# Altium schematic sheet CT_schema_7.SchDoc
size 250 x 169 mm
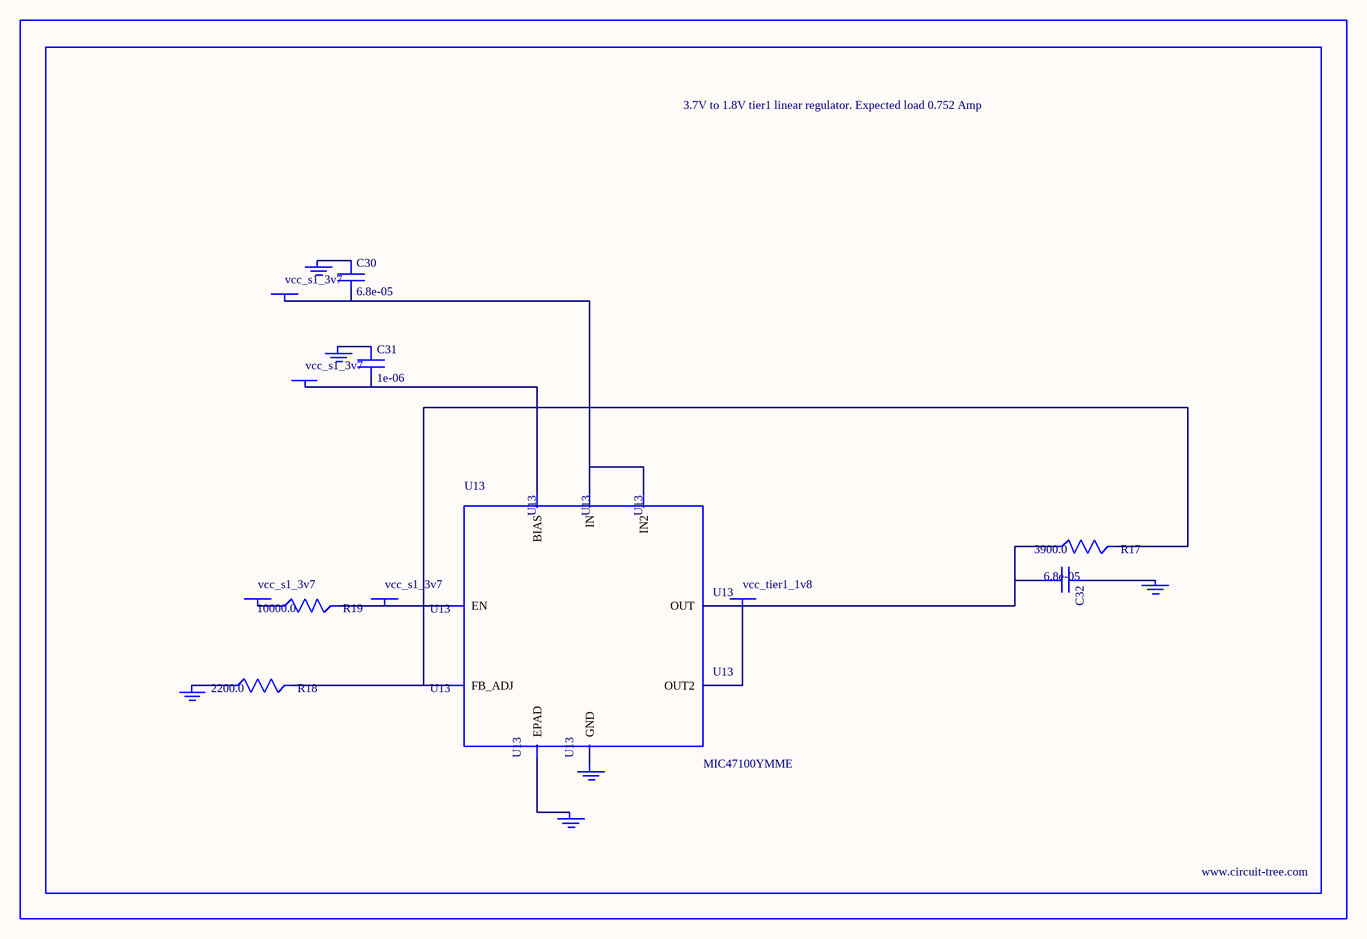
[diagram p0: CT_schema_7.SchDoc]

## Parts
BORDER6  (no value)
C30  6.8e-05  [2220]
C31  1e-06  [C0603]
C32  6.8e-05  [2220]
GND_INSTANCE_6_0  (no value)
GND_INSTANCE_6_1  (no value)
GND_INSTANCE_6_2  (no value)
GND_INSTANCE_6_3  (no value)
GND_INSTANCE_6_4  (no value)
GND_INSTANCE_6_5  (no value)
POWER_INSTANCE_6_0  vcc_s1_3v7
POWER_INSTANCE_6_1  vcc_s1_3v7
POWER_INSTANCE_6_2  vcc_s1_3v7
POWER_INSTANCE_6_3  vcc_s1_3v7
POWER_INSTANCE_6_4  vcc_tier1_1v8
R17  3900.0  [R0603]
R18  2200.0  [R0603]
R19  10000.0  [R0603]
U13  MIC47100YMME  [MSOP-8_EP]

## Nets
NetC30_1: C30.1 GND_INSTANCE_6_0.0(GND)
NetC30_2: C30.2 POWER_INSTANCE_6_0.0(PWR) U13.1(IN) U13.2(IN2)
NetC31_1: C31.1 GND_INSTANCE_6_1.0(GND)
NetC31_2: C31.2 POWER_INSTANCE_6_1.0(PWR) U13.4(BIAS)
NetC32_1: C32.1 GND_INSTANCE_6_3.0(GND)
NetC32_2: C32.2 POWER_INSTANCE_6_4.0(PWR) R17.1 U13.7(OUT) U13.8(OUT2)
NetGND_INSTANCE_6_2_0: GND_INSTANCE_6_2.0(GND) R18.1
NetGND_INSTANCE_6_4_0: GND_INSTANCE_6_4.0(GND) U13.EPAD
NetGND_INSTANCE_6_5_0: GND_INSTANCE_6_5.0(GND) U13.3(GND)
NetPOWER_INSTANCE_6_2_0: POWER_INSTANCE_6_2.0(PWR) R19.1
NetPOWER_INSTANCE_6_3_0: POWER_INSTANCE_6_3.0(PWR) R19.2 U13.5(EN)
NetR17_2: R17.2 R18.2 U13.6(FB_ADJ)

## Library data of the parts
BORDER6 = BORDER_PAGE6
C30 C32 = C5750X5R1A686M
C31 = C0603C105K3RACTU
GND_INSTANCE_6_0-GND_INSTANCE_6_5 = GND
POWER_INSTANCE_6_0-POWER_INSTANCE_6_4 = PWR
R17 = RC0603JR-073K9L
R18 = RC0603JR-072K2L
R19 = RC0603JR-0710KL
